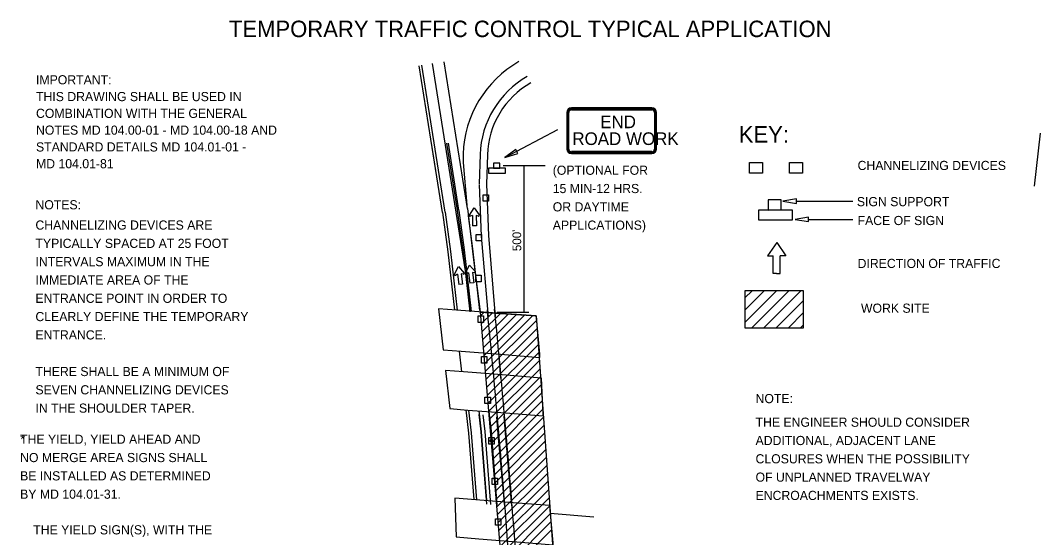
# Model space of a CAD drawing. Extents: x 612.5 to 619.9, y 600.8 to 610.9.
# Drawn here: x 612.65 to 619.33, y 607.47 to 610.86 of the extents above; entities that cross this region are included whole.
import ezdxf

# ---------------------------------------------------------------- set-up
doc = ezdxf.new("R2010")
doc.units = 0
for name, color, linetype in [('DETL-DIMS', 7, 'Continuous'), ('DETL-LINE', 7, 'Continuous'), ('DETL-NOTE', 7, 'Continuous'), ('DETL-TITL', 7, 'Continuous'), ('USER-BORD', 7, 'Continuous')]:
    doc.layers.add(name, color=color, linetype=linetype)

# ---------------------------------------------------------------- blocks, each defined once
blk = doc.blocks.new('DIR3')
at = {"layer": 'USER-BORD'}
for p, q in [((0, 0.0012), (-0.0342, -0.0477)), ((0, 0.0012), (0.0342, -0.0477)), ((-0.0342, -0.0477), (-0.0132, -0.0477)), ((-0.0132, -0.1133), (-0.0132, -0.0477)), ((0.0342, -0.0477), (0.0132, -0.0477)), ((0.0132, -0.1133), (0.0132, -0.0477)), ((-0.0011, -0.1133), (-0.0132, -0.1133)), ((-0.0011, -0.1133), (0.0011, -0.1133)), ((0.0011, -0.1133), (0.0132, -0.1133))]:
    blk.add_line(p, q, dxfattribs=at)
blk = doc.blocks.new('SIGN14')
at = {"layer": 'USER-BORD'}
for points in [[(-0.0134, 0.0182), (0.011, 0.0189), (0.011, 0.0371), (-0.0134, 0.0371)], [(-0.0314, 0.0182), (-0.0314, 0), (0.032, 0), (0.032, 0.0182)]]:
    blk.add_lwpolyline(points, close=True, dxfattribs=at)

msp = doc.modelspace()

# ---------------------------------------------------------------- linework, layer by layer
at = {"layer": 'DETL-DIMS'}
for p, q in [((615.8227, 609.9618), (616.1686, 610.1451)), ((615.8106, 609.9092), (616.087, 609.9092)), ((615.9492, 608.9492), (615.9492, 609.9092)), ((617.7326, 609.6757), (618.1015, 609.6757)), ((617.8114, 609.5565), (618.1015, 609.5565)), ((615.7721, 608.9492), (615.9797, 608.9492))]:
    msp.add_line(p, q, dxfattribs=at)
for points in [[(615.9076, 609.9893), (615.894, 610.0154), (615.8227, 609.9618)], [(617.7326, 609.661), (617.7326, 609.6904), (617.6446, 609.6757)], [(617.8114, 609.5418), (617.8114, 609.5712), (617.7234, 609.5565)]]:
    msp.add_lwpolyline(points, close=True, dxfattribs=at)
at = {"layer": 'DETL-LINE'}
for p, q in [((616.7854, 610.287), (616.2584, 610.287)), ((616.2584, 610.2809), (616.7854, 610.2809)), ((616.2584, 610.2746), (616.7854, 610.2746)), ((616.2286, 610.2573), (616.2286, 610.0176)), ((616.2347, 610.0176), (616.2347, 610.2573)), ((616.241, 610.0176), (616.241, 610.2573)), ((616.8025, 610.2573), (616.8025, 610.0176)), ((616.8026, 610.2571), (616.8025, 610.2573)), ((616.8094, 610.2573), (616.8094, 610.0176)), ((616.8155, 610.0176), (616.8155, 610.2573)), ((616.7854, 610.0005), (616.2584, 610.0005)), ((615.5489, 609.9812), (615.5489, 609.9555)), ((615.5499, 609.9301), (615.5738, 609.6504)), ((616.7854, 609.9936), (616.2584, 609.9936)), ((616.2584, 609.9876), (616.7854, 609.9876)), ((615.5775, 609.6269), (615.6188, 609.2749)), ((615.5899, 609.5849), (615.6215, 609.6333)), ((615.6215, 609.6333), (615.6546, 609.5862)), ((615.6098, 609.5825), (615.5954, 609.5775)), ((615.6098, 609.5825), (615.6116, 609.5145)), ((615.6494, 609.5786), (615.6347, 609.5831)), ((615.6347, 609.5831), (615.6362, 609.5148)), ((615.6362, 609.5148), (615.6116, 609.5145)), ((615.6188, 609.2749), (615.6607, 608.9502)), ((615.492, 609.1972), (615.5185, 609.2483)), ((615.5121, 609.1966), (615.4982, 609.1899)), ((615.5121, 609.1966), (615.5206, 609.1291)), ((615.5185, 609.2483), (615.5563, 609.2047)), ((615.5519, 609.1967), (615.5367, 609.1997)), ((615.5367, 609.1997), (615.545, 609.132)), ((615.5653, 609.2062), (615.5918, 609.2573)), ((615.5854, 609.2056), (615.5716, 609.1989)), ((615.5854, 609.2056), (615.5939, 609.1381)), ((615.5918, 609.2573), (615.6296, 609.2137)), ((615.6253, 609.2057), (615.61, 609.2087)), ((615.61, 609.2087), (615.6184, 609.141)), ((615.545, 609.132), (615.5206, 609.1291)), ((615.6184, 609.141), (615.5939, 609.1381)), ((617.7787, 609.0886), (617.3952, 609.0886)), ((617.3952, 609.0886), (617.3952, 608.8467)), ((617.3952, 608.8818), (617.6021, 609.0886)), ((617.3952, 608.9617), (617.5222, 609.0886)), ((617.3952, 609.0416), (617.4422, 609.0886)), ((617.4402, 608.8467), (617.682, 609.0886)), ((617.52, 608.8467), (617.762, 609.0886)), ((617.7787, 608.8467), (617.7787, 609.0886)), ((617.5999, 608.8467), (617.7788, 609.0255)), ((615.6659, 608.9261), (615.6881, 608.9483)), ((615.6703, 608.8739), (615.7409, 608.9445)), ((615.6747, 608.8217), (615.7936, 608.9407)), ((615.6791, 608.7695), (615.8464, 608.9369)), ((615.6834, 608.7174), (615.8992, 608.9331)), ((615.6878, 608.6652), (615.952, 608.9293)), ((617.6798, 608.8467), (617.7788, 608.9456)), ((615.6922, 608.613), (616.0047, 608.9255)), ((615.6966, 608.5608), (616.0311, 608.8954)), ((617.7598, 608.8467), (617.7788, 608.8657)), ((615.7009, 608.5086), (616.0344, 608.8421)), ((617.3952, 608.8467), (617.7787, 608.8467)), ((615.7053, 608.4564), (616.0382, 608.7892)), ((615.7097, 608.4042), (616.0419, 608.7364)), ((615.5228, 608.6937), (615.5382, 608.5579)), ((615.7116, 608.3495), (616.0456, 608.6835)), ((615.7173, 608.2986), (616.0493, 608.6307)), ((615.7828, 608.6509), (615.7944, 608.5153)), ((615.7229, 608.2477), (616.053, 608.5778)), ((615.7298, 608.1981), (616.0567, 608.525)), ((615.7339, 608.1456), (616.0605, 608.4721)), ((615.7381, 608.0931), (616.0642, 608.4193)), ((615.7422, 608.0407), (616.0679, 608.3664)), ((615.7175, 608.2965), (615.7331, 608.1559)), ((615.7463, 607.9882), (616.0716, 608.3136)), ((615.7504, 607.9358), (616.0753, 608.2607)), ((615.7545, 607.8833), (616.0791, 608.2079)), ((615.7563, 607.8285), (616.0828, 608.155)), ((615.7399, 608.0968), (615.7272, 608.1064)), ((615.7373, 608.0959), (615.7272, 608.1037)), ((615.7336, 608.0963), (615.728, 608.1006)), ((615.7423, 608.0983), (615.7281, 608.1083)), ((615.7435, 608.1002), (615.7296, 608.1103)), ((615.7442, 608.1018), (615.731, 608.1117)), ((615.7447, 608.1046), (615.7337, 608.1133)), ((615.744, 608.1075), (615.7367, 608.1134)), ((615.7627, 607.7784), (616.0865, 608.1022)), ((615.7668, 607.7259), (616.0902, 608.0493)), ((615.7709, 607.6735), (616.0939, 607.9965)), ((615.7753, 607.6213), (616.0976, 607.9436)), ((615.7797, 607.5691), (616.1014, 607.8908)), ((615.784, 607.5169), (616.1051, 607.8379)), ((615.7884, 607.4647), (616.1088, 607.7851)), ((615.7928, 607.4125), (616.1125, 607.7322)), ((615.7972, 607.3603), (616.1162, 607.6794)), ((615.8015, 607.3081), (616.12, 607.6265)), ((615.8059, 607.2559), (616.1237, 607.5737)), ((615.8103, 607.2037), (616.1274, 607.5208))]:
    msp.add_line(p, q, dxfattribs=at)
for points in [[(615.4134, 609.601), (615.2611, 610.5641)], [(615.431, 609.6038), (615.2787, 610.5669)], [(615.5641, 609.2204), (615.3494, 610.5781)], [(615.5775, 609.6269), (615.4252, 610.5901)], [(619.2919, 609.7739), (619.3323, 610.1221)], [(619.2919, 609.7739), (619.3323, 610.1221)], [(615.4134, 609.601), (615.3413, 610.0569)], [(615.513, 609.6167), (615.4434, 610.0569)], [(615.6605, 609.9811), (615.6546, 609.7889)], [(615.708, 609.9796), (615.702, 609.7875)], [(615.6546, 609.7855), (615.6679, 609.4472), (615.7127, 608.9169)], [(615.702, 609.7874), (615.7153, 609.4501), (615.7599, 608.9209)], [(615.4133, 609.601), (615.4484, 609.3431), (615.4921, 608.9622)], [(615.431, 609.6034), (615.4661, 609.3454), (615.5101, 608.961)], [(615.5949, 608.9514), (615.5486, 609.3557), (615.5133, 609.6146)], [(615.6597, 608.9589), (615.6133, 609.3639), (615.5838, 609.5805)], [(615.5641, 609.2205), (615.5945, 608.9549)], [(615.3878, 608.9698), (615.418, 608.702)], [(615.418, 608.702), (615.5365, 608.6926), (615.794, 608.6723), (616.0525, 608.652), (616.0507, 608.6729), (616.0316, 608.8904), (616.0287, 608.9238), (615.7711, 608.9423), (615.5058, 608.9613), (615.3878, 608.9698)], [(615.4334, 608.5662), (615.4615, 608.3165)], [(615.4615, 608.3165), (615.5807, 608.3072), (615.8264, 608.2879), (616.0732, 608.2687), (616.0728, 608.2803), (616.0632, 608.5152), (616.0632, 608.5163), (615.8055, 608.5368), (615.552, 608.5568), (615.4334, 608.5662)], [(615.567, 608.3083), (615.5845, 608.1556), (615.593, 608.0457)], [(615.585, 608.3069), (615.6022, 608.1573), (615.6108, 608.0465)], [(615.6513, 608.3017), (615.6672, 608.1636), (615.6759, 608.0516)], [(615.6761, 608.0495), (615.6671, 608.1636), (615.654, 608.2782)], [(615.7203, 608.273), (615.7321, 608.1698), (615.7413, 608.0525)], [(615.768, 608.2626), (615.7798, 608.1226), (615.7859, 608.0545)], [(615.8153, 608.2666), (615.8271, 608.1267), (615.8333, 608.0567)], [(615.7331, 608.1559), (615.7682, 607.7081)], [(615.593, 608.0457), (615.6186, 607.7197)], [(615.6108, 608.0465), (615.6365, 607.7183)], [(615.6759, 608.0516), (615.7024, 607.7132)], [(615.7042, 607.6898), (615.6761, 608.0495)], [(615.7413, 608.0525), (615.7701, 607.6847)], [(615.7859, 608.0545), (615.8196, 607.6741)], [(615.8333, 608.0567), (615.8669, 607.6783)], [(615.8333, 608.0567), (615.8669, 607.6783)], [(615.8333, 608.0567), (615.8669, 607.6783)], [(615.4938, 607.7293), (615.5034, 607.4759)], [(615.5034, 607.4759), (615.6514, 607.4639), (615.9007, 607.4435), (616.14, 607.424), (616.139, 607.4356), (616.1204, 607.6527), (616.1179, 607.6811), (615.878, 607.6997), (615.6314, 607.7187), (615.4938, 607.7293)], [(616.1201, 607.6305), (616.4051, 607.6072)]]:
    msp.add_lwpolyline(points, dxfattribs=at)
for points in [[(617.4255, 609.8586), (617.4255, 609.9296), (617.5099, 609.9296), (617.5099, 609.8586)], [(617.6882, 609.8586), (617.6882, 609.9296), (617.7726, 609.9296), (617.7726, 609.8586)], [(615.7164, 609.6758), (615.681, 609.6758), (615.681, 609.718), (615.7164, 609.718)], [(615.6698, 609.4151), (615.6344, 609.4151), (615.6344, 609.4573), (615.6698, 609.4573)], [(615.6676, 609.1478), (615.6322, 609.1478), (615.6322, 609.19), (615.6676, 609.19)], [(616.162, 607.0297), (615.8227, 607.0555), (615.664, 608.9494), (616.0287, 608.9238)], [(615.6832, 608.8815), (615.6477, 608.8815), (615.6477, 608.9237), (615.6832, 608.9237)], [(615.7054, 608.6153), (615.6699, 608.6153), (615.6699, 608.6575), (615.7054, 608.6575)], [(615.7276, 608.349), (615.6921, 608.349), (615.6921, 608.3912), (615.7276, 608.3912)], [(615.7531, 608.0839), (615.7176, 608.0839), (615.7176, 608.1261), (615.7531, 608.1261)], [(615.7753, 607.8187), (615.7398, 607.8187), (615.7398, 607.8609), (615.7753, 607.8609)], [(615.7963, 607.5524), (615.7608, 607.5524), (615.7608, 607.5946), (615.7963, 607.5946)]]:
    msp.add_lwpolyline(points, close=True, dxfattribs=at)
msp.add_circle((615.7359, 608.1047), 0.0089, dxfattribs=at)
for centre, radius, start, end in [((616.2712, 609.962), 0.7226, 119.57405, 178.20893), ((616.2712, 609.962), 0.6109, 119.57405, 178.20893), ((616.2712, 609.962), 0.5635, 119.57405, 178.20893), ((616.2584, 610.2569), 0.03, 90, 180), ((616.2584, 610.2569), 0.024, 90, 180), ((616.2584, 610.2569), 0.0172, 90, 180), ((616.7853, 610.2569), 0.03, 0, 90), ((616.7853, 610.2569), 0.024, 0, 90), ((616.7853, 610.2569), 0.0172, 0, 90), ((616.2584, 610.0175), 0.03, 180, 270), ((616.2584, 610.0175), 0.024, 180, 270), ((616.2584, 610.0175), 0.0172, 180, 270), ((616.7853, 610.0175), 0.03, 270, 0), ((616.7853, 610.0175), 0.0172, 270, 0), ((616.7853, 610.0175), 0.024, 270, 0), ((615.8455, 609.9553), 0.2966, 179.95504, 184.86673), ((615.5941, 609.5822), 0.00489, 146.90829, 289.1686), ((615.6509, 609.5834), 0.00489, 253.16862, 35.42893), ((615.4963, 609.1947), 0.00489, 152.67143, 294.93174), ((615.5528, 609.2016), 0.00489, 258.93176, 41.19207), ((615.5696, 609.2037), 0.00489, 152.67143, 294.93174), ((615.6261, 609.2106), 0.00489, 258.93176, 41.19207), ((545.2135, 602.0274), 70.8351, 4.017322, 5.619484), ((545.2135, 602.0274), 70.8825, 4.017322, 5.619484)]:
    msp.add_arc(centre, radius, start, end, dxfattribs=at)
at = {"layer": 'DETL-TITL'}
for points in [[(615.5218, 609.6181), (615.4524, 610.0569)], [(615.6037, 608.9524), (615.5574, 609.3568), (615.5222, 609.6158)], [(615.7027, 608.0507), (615.6937, 608.1661), (615.6811, 608.276)], [(615.7312, 607.6877), (615.7027, 608.0507)]]:
    msp.add_lwpolyline(points, dxfattribs=at)

# ---------------------------------------------------------------- block references
at = {"layer": 'DETL-LINE'}
for name, p, xscale, yscale in [('SIGN14', (615.7707, 609.8597), 1.7600000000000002, 1.7600000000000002), ('SIGN14', (617.5943, 609.5531), 3.5200000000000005, 3.5200000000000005), ('DIR3', (617.6038, 609.4024), 1.7600000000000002, 1.7600000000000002)]:
    msp.add_blockref(name, p, dxfattribs=dict(at, xscale=xscale, yscale=yscale))

# ---------------------------------------------------------------- texts
for s, p in [('END', (616.4473, 610.1544)), ('ROAD WORK', (616.2649, 610.0442))]:
    msp.add_text(s, height=0.08294, rotation=360, dxfattribs=at).set_placement(p)
at = {"layer": 'DETL-NOTE'}
for s, height, p in [('IMPORTANT:', 0.06, (612.7511, 610.4416)), ('THIS DRAWING SHALL BE USED IN', 0.06, (612.7511, 610.3316)), ('COMBINATION WITH THE GENERAL', 0.06, (612.7511, 610.2216)), ('NOTES MD 104.00-01 - MD 104.00-18 AND', 0.06, (612.7511, 610.1116)), ('STANDARD DETAILS MD 104.01-01 -', 0.06, (612.7511, 610.0016)), ('MD 104.01-81', 0.06, (612.7511, 609.8916)), ('CHANNELIZING DEVICES', 0.06, (618.1334, 609.8801)), ('(OPTIONAL FOR', 0.06, (616.1364, 609.8489)), ('15 MIN-12 HRS. ', 0.06, (616.1364, 609.7289)), ('NOTES:', 0.06, (612.7474, 609.6223)), ('OR DAYTIME', 0.06, (616.1364, 609.6089)), ('SIGN SUPPORT', 0.06, (618.1286, 609.6431)), ('CHANNELIZING DEVICES ARE ', 0.06, (612.7474, 609.4896)), ('APPLICATIONS)', 0.06, (616.1364, 609.4889)), ('FACE OF SIGN', 0.06, (618.1334, 609.5193)), ('TYPICALLY SPACED AT 25 FOOT ', 0.06, (612.7474, 609.3696)), ('INTERVALS MAXIMUM IN THE ', 0.06, (612.7474, 609.2496)), ('DIRECTION OF TRAFFIC', 0.06, (618.1334, 609.238)), ('IMMEDIATE AREA OF THE ', 0.06, (612.7474, 609.1296)), ('ENTRANCE POINT IN ORDER TO ', 0.06, (612.7474, 609.0096)), ('WORK SITE', 0.06, (618.1555, 608.9446)), ('CLEARLY DEFINE THE TEMPORARY ', 0.06, (612.7474, 608.8896)), ('ENTRANCE.', 0.06, (612.7474, 608.7696)), ('THERE SHALL BE A MINIMUM OF ', 0.06, (612.7474, 608.5296)), ('SEVEN CHANNELIZING DEVICES ', 0.06, (612.7474, 608.4096)), ('NOTE:', 0.06, (617.4648, 608.3521)), ('IN THE SHOULDER TAPER.', 0.06, (612.7474, 608.2896)), ('THE ENGINEER SHOULD CONSIDER', 0.06, (617.4649, 608.1974)), ('  THE YIELD, YIELD AHEAD AND ', 0.06, (612.6025, 608.0857)), ('*', 0.057, (612.6488, 608.0873)), ('ADDITIONAL, ADJACENT LANE', 0.06, (617.4649, 608.0774)), ('  NO MERGE AREA SIGNS SHALL', 0.06, (612.6025, 607.9657)), ('CLOSURES WHEN THE POSSIBILITY', 0.06, (617.4649, 607.9574)), ('  BE INSTALLED AS DETERMINED', 0.06, (612.6025, 607.8457)), ('OF UNPLANNED TRAVELWAY', 0.06, (617.4649, 607.8374)), ('  BY MD 104.01-31.', 0.06, (612.6025, 607.7257)), ('ENCROACHMENTS EXISTS.', 0.06, (617.4649, 607.7174)), ('THE YIELD SIGN(S), WITH THE ', 0.06, (612.7328, 607.492))]:
    msp.add_text(s, height=height, dxfattribs=at).set_placement(p)
msp.add_text("500'", height=0.057, rotation=90.40483, dxfattribs=at).set_placement((615.9301, 609.3483))
at = {"layer": 'DETL-TITL'}
for s, p in [('TEMPORARY TRAFFIC CONTROL TYPICAL APPLICATION', (614.0149, 610.7512)), ('KEY:', (617.3546, 610.0597))]:
    msp.add_text(s, height=0.108, dxfattribs=at).set_placement(p)

doc.saveas('drawing.dxf')
